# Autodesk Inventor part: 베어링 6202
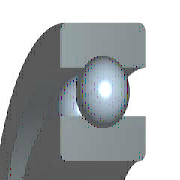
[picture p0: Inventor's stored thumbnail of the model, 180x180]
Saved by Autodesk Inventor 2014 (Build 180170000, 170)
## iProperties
IsCustomPart: 1
Created: 2015-09
Part Number: 베어링 6202
Material: 강철, 연강
Description: 깊은 그루브 볼 베어링
Document SubType Name: Modeling
Standard: KS B 2023
Designer: mduedu
Standards Organization: KS
Language: ko-KR
Size Designation: 6202 - 15 x 35 x 11
Categories: <MemberInstance><Categories><Category DisplayName="샤프트 부품" InternalName="7f7aeb1f-a693-4053-b835-cee3144e0d98" Mnemonic="SHFT"><Category DisplayName="베어링" Inter
Density: 7.86 g/cm^3
Mass: 45.8725 g
Surface Area: 51.5584 cm^2
Volume: 5.83619 cm^3
Appearance: Yellow
Author: mduedu
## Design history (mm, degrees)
sketch "스케치" dims "d0" = 5.2 (= -0.26 x WD + 0.26 x BD)
  geometry: L1 (2.9, 12.5)-(8.1, 12.5); L2 (5.5, 12.5)-(5.5, 9.9); L3 (5.5, 12.5)-(5.5, 15.1); L4 (3.568, 10.76)-(0, 10.76); L5 (0, 7.5)-(11, 7.5); L6 (3.568, 14.24)-(0, 14.24); L7 (0, 17.5)-(11, 17.5); L8 (11, 7.5)-(11, 10.76); L9 (7.432, 10.76)-(11, 10.76); L10 (7.432, 14.24)-(11, 14.24); L11 (11, 17.5)-(11, 14.24); L12 (-1.4, 0)-(8.4, 0) reference; L13 (0, -0.3)-(0, 5.3) reference
  constraints: 22 end point, 4 point on line, 2 collinear, 2 perpendicular, 2 symmetric about line, 1 midpoint, 1 parallel, 14 other
  dimensions: "d9" = 15 diameter of L5 L12 (= WD); "d11" = 35 diameter of L7 L12 (= BD); "d12" = 11 distance between parallel lines of L8 L13 (= KB); "d13" = 21.52 diameter of L9 L12 (= 0.326 x BD + 0.674 x WD)
revolve "본체" stored, may be unused: angle "d6" = 90 deg
revolve "볼" stored, may be unused: angle "d7" = 90 deg
pattern_circular "IDS_ARRAYBALL[SIMPL:T]" dims angle "d3" = 360 deg
body "Solid1"
fillet "모깎기1" dims "d1" = 0.6 (= KRS)
other parameters: "WD" = 15 [user parameter; used in 5 equation terms], "BD" = 35 [user parameter; used in 5 equation terms], "KB" = 11 [user parameter; used in 1 equation term], "KRS" = 0.6 [user parameter; used in 1 equation term], "d4" = 0, "d5" = 0, "d8" = 0, "d14" = 0, "d15" = 0, "BBA" = 0 [user parameter], "BC0" = 3750000 [user parameter], "BC" = 7800000 [user parameter], "BR" = 17.5 (= 0.5 x BD) [user parameter], "WR" = 7.5 (= 0.5 x WD) [user parameter]
